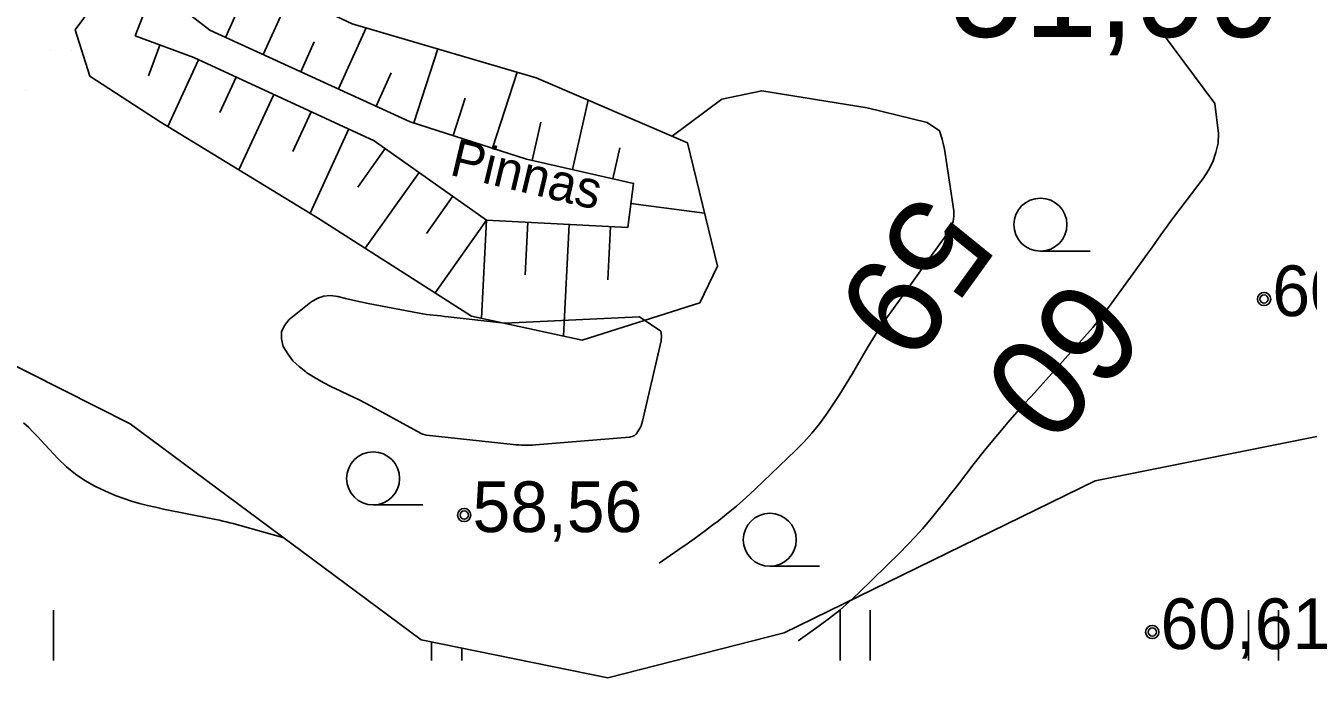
# Model space of a CAD drawing. Extents: x 532503 to 539665, y 6557663 to 6561526.
# Drawn here: x 535438.1 to 535500.1, y 6559470.5 to 6559502.2 of the extents above; entities that cross this region are included whole.
import ezdxf

# ---------------------------------------------------------------- set-up
doc = ezdxf.new("R2010")
doc.units = 0
for name, color, linetype in [('Default', 7, 'Continuous'), ('GEOLPUNKT', 7, 'Continuous'), ('HALJASTUS', 7, 'Continuous'), ('HORISONTAAL-EH2000', 7, 'Continuous'), ('KORGUS-EH2000', 7, 'Continuous'), ('RELJEEF', 7, 'Continuous')]:
    doc.layers.add(name, color=color, linetype=linetype)

# ---------------------------------------------------------------- blocks, each defined once
blk = doc.blocks.new('POINT_DISPLAY')
at = {"layer": 'Default'}
blk.add_line((0, 0), (0, 0), dxfattribs=at)

msp = doc.modelspace()

# ---------------------------------------------------------------- linework, layer by layer
at = {"layer": 'HALJASTUS'}
for p, q in [((535487.165, 6559491.333), (535489.565, 6559491.333)), ((535454.926, 6559479.07), (535457.326, 6559479.07)), ((535474.092, 6559476.103), (535476.492, 6559476.103)), ((535439.479, 6559471.546), (535439.479, 6559473.982)), ((535477.484, 6559471.546), (535477.484, 6559473.982)), ((535478.941, 6559471.546), (535478.941, 6559473.982)), ((535497.215, 6559471.546), (535497.215, 6559473.982)), ((535498.671, 6559471.546), (535498.671, 6559473.982)), ((535457.753, 6559471.546), (535457.753, 6559472.453)), ((535459.21, 6559471.546), (535459.21, 6559472.156))]:
    msp.add_line(p, q, dxfattribs=at)
msp.add_lwpolyline([(535297.765, 6559425.333), (535293.237, 6559472.388), (535292.11, 6559493.515), (535294.197, 6559495.477), (535329.337, 6559492.847), (535343.026, 6559489.84), (535371.406, 6559495.352), (535400.286, 6559496.521), (535423.657, 6559492.847), (535443.189, 6559482.993), (535457.253, 6559472.555), (535466.268, 6559470.718), (535474.782, 6559472.889), (535489.806, 6559480.237), (535512.343, 6559484.747), (535525.539, 6559485.647)], dxfattribs=at)
for centre in [(535487.165, 6559492.613), (535454.926, 6559480.35), (535474.092, 6559477.383)]:
    msp.add_circle(centre, 1.28, dxfattribs=at)
at = {"layer": 'HORISONTAAL-EH2000'}
for points in [[(535495.591, 6559498.47), (535492.597, 6559502.5), (535492.917, 6559507.664)], [(535482.418, 6559496.737), (535482.287, 6559497.155), (535481.687, 6559497.552), (535478.792, 6559498.26), (535473.707, 6559499.083), (535471.782, 6559498.686), (535469.379, 6559496.884)], [(535489.695, 6559487.636), (535490.101, 6559488.15), (535490.577, 6559488.782), (535492.117, 6559490.903), (535492.308, 6559491.168), (535492.498, 6559491.433), (535492.687, 6559491.699), (535492.875, 6559491.966), (535493.063, 6559492.232), (535493.254, 6559492.496), (535493.448, 6559492.759), (535493.644, 6559493.02), (535495.032, 6559494.849), (535495.287, 6559495.244), (535495.5, 6559495.657), (535495.648, 6559496.097), (535495.753, 6559496.555), (535495.767, 6559497.014), (535495.591, 6559498.47)], [(535482.358, 6559491.751), (535482.401, 6559491.809), (535482.498, 6559491.947), (535482.595, 6559492.084), (535482.691, 6559492.223), (535482.731, 6559492.28), (535482.8, 6559492.393), (535482.861, 6559492.51), (535482.909, 6559492.632), (535482.949, 6559492.758), (535482.975, 6559492.888), (535482.989, 6559493.018), (535482.988, 6559493.149), (535482.977, 6559493.28), (535482.562, 6559496.055), (535482.527, 6559496.26), (535482.486, 6559496.464), (535482.438, 6559496.666), (535482.418, 6559496.737)], [(535468.75, 6559476.25), (535469.651, 6559476.875), (535470.099, 6559477.19), (535470.545, 6559477.51), (535470.986, 6559477.835), (535471.424, 6559478.164), (535471.526, 6559478.241), (535472.006, 6559478.62), (535472.477, 6559479.009), (535472.935, 6559479.414), (535473.384, 6559479.83), (535475.329, 6559481.694), (535475.736, 6559482.108), (535476.126, 6559482.538), (535476.489, 6559482.99), (535476.835, 6559483.457), (535477.161, 6559483.939), (535477.479, 6559484.427), (535477.785, 6559484.922), (535478.082, 6559485.423), (535478.389, 6559485.957), (535478.845, 6559486.721), (535479.317, 6559487.475), (535479.812, 6559488.213), (535479.903, 6559488.343), (535482.358, 6559491.751)], [(535461.296, 6559487.845), (535458.554, 6559488.163), (535458.379, 6559488.182), (535458.203, 6559488.201), (535458.028, 6559488.218), (535457.852, 6559488.234), (535457.676, 6559488.252), (535457.501, 6559488.273), (535457.327, 6559488.3), (535457.153, 6559488.331), (535454.689, 6559488.809), (535454.321, 6559488.884), (535453.954, 6559488.964), (535453.59, 6559489.052), (535453.226, 6559489.144), (535452.875, 6559489.184), (535452.537, 6559489.162), (535452.219, 6559489.046), (535451.914, 6559488.867), (535450.878, 6559488.036), (535450.645, 6559487.745), (535450.503, 6559487.435), (535450.499, 6559487.093), (535450.586, 6559486.731), (535450.801, 6559486.37), (535451.049, 6559486.039), (535451.347, 6559485.751), (535451.678, 6559485.494), (535451.731, 6559485.459), (535452.121, 6559485.216), (535452.517, 6559484.986), (535452.924, 6559484.775), (535453.337, 6559484.576), (535453.765, 6559484.377), (535454.182, 6559484.174), (535454.595, 6559483.963), (535455.004, 6559483.746), (535457.254, 6559482.52), (535457.272, 6559482.51), (535457.291, 6559482.502), (535457.31, 6559482.494), (535457.33, 6559482.487), (535457.449, 6559482.449), (535457.5, 6559482.44), (535461.692, 6559481.989), (535461.827, 6559481.977), (535461.961, 6559481.966), (535462.096, 6559481.96), (535462.23, 6559481.955), (535462.365, 6559481.954), (535462.5, 6559481.957), (535462.634, 6559481.963), (535462.769, 6559481.972), (535467.309, 6559482.345), (535467.328, 6559482.347), (535467.348, 6559482.35), (535467.367, 6559482.354), (535467.386, 6559482.359), (535467.462, 6559482.38), (535467.481, 6559482.386), (535467.498, 6559482.394), (535467.515, 6559482.403), (535467.532, 6559482.414), (535467.611, 6559482.473), (535467.629, 6559482.487), (535467.645, 6559482.503), (535467.66, 6559482.521), (535467.673, 6559482.539), (535467.768, 6559482.694), (535467.823, 6559482.793), (535467.871, 6559482.895), (535467.909, 6559483.002), (535467.94, 6559483.111), (535468.841, 6559486.998), (535468.856, 6559487.236), (535468.826, 6559487.46), (535467.795, 6559488.159), (535461.296, 6559487.845)], [(535475.46, 6559472.5), (535476.48, 6559473.223), (535476.981, 6559473.595), (535477.468, 6559473.983), (535477.937, 6559474.393), (535478.394, 6559474.819), (535480.369, 6559476.75), (535480.746, 6559477.131), (535481.115, 6559477.52), (535481.471, 6559477.92), (535481.818, 6559478.328), (535482.157, 6559478.743), (535482.493, 6559479.161), (535482.825, 6559479.582), (535483.154, 6559480.005), (535483.972, 6559481.069), (535484.531, 6559481.778), (535485.101, 6559482.476), (535485.688, 6559483.161), (535486.287, 6559483.836), (535486.436, 6559484), (535486.896, 6559484.506), (535489.695, 6559487.636)], [(535438.041, 6559483.039), (535438.166, 6559482.928), (535438.286, 6559482.812), (535438.322, 6559482.776), (535438.456, 6559482.637), (535438.59, 6559482.498), (535438.723, 6559482.359), (535438.855, 6559482.218), (535439.711, 6559481.303), (535440.114, 6559480.916), (535440.541, 6559480.562), (535441.003, 6559480.255), (535441.49, 6559479.981), (535441.787, 6559479.834), (535442.147, 6559479.667), (535442.512, 6559479.513), (535442.885, 6559479.377), (535443.262, 6559479.253), (535443.644, 6559479.144), (535444.028, 6559479.042), (535444.415, 6559478.952), (535444.804, 6559478.868), (535447.163, 6559478.399), (535447.331, 6559478.364), (535447.499, 6559478.328), (535447.666, 6559478.289), (535447.833, 6559478.249), (535448, 6559478.207), (535448.166, 6559478.164), (535448.331, 6559478.12), (535448.497, 6559478.074), (535450.56, 6559477.5)]]:
    msp.add_lwpolyline(points, dxfattribs=at)
at = {"layer": 'KORGUS-EH2000'}
for centre, radius in [((535497.971, 6559489.018), 0.32), ((535497.971, 6559489.018), 0.2), ((535459.329, 6559478.579), 0.32), ((535459.329, 6559478.579), 0.2), ((535459.329, 6559478.579), 0.2), ((535492.571, 6559472.925), 0.32), ((535492.571, 6559472.925), 0.2), ((535492.571, 6559472.925), 0.2)]:
    msp.add_circle(centre, radius, dxfattribs=at)
at = {"layer": 'RELJEEF'}
for p, q in [((535449.609, 6559500.834), (535450.931, 6559503.731)), ((535447.79, 6559501.664), (535448.455, 6559503.123)), ((535453.248, 6559499.173), (535454.596, 6559502.126)), ((535451.428, 6559500.003), (535452.085, 6559501.442)), ((535444.622, 6559501.295), (535444.071, 6559499.804)), ((535456.894, 6559497.531), (535458.046, 6559501.11)), ((535446.491, 6559500.585), (535445.005, 6559497.36)), ((535448.307, 6559499.748), (535447.515, 6559498.029)), ((535455.067, 6559498.342), (535455.801, 6559499.949)), ((535460.702, 6559496.306), (535461.885, 6559499.98)), ((535450.124, 6559498.911), (535448.442, 6559495.262)), ((535458.798, 6559496.919), (535459.382, 6559498.732)), ((535464.563, 6559495.275), (535465.322, 6559498.627)), ((535451.94, 6559498.074), (535451.051, 6559496.143)), ((535453.757, 6559497.237), (535451.88, 6559493.164)), ((535462.612, 6559495.717), (535463.033, 6559497.574)), ((535455.513, 6559496.296), (535454.187, 6559494.422)), ((535466.513, 6559494.833), (535466.852, 6559496.329)), ((535457.146, 6559495.141), (535454.548, 6559491.47)), ((535458.779, 6559493.986), (535457.507, 6559492.189)), ((535467.384, 6559493.639), (535470.935, 6559493.171)), ((535460.411, 6559492.831), (535457.923, 6559489.314)), ((535460.411, 6559492.831), (535460.166, 6559488.089)), ((535462.409, 6559492.727), (535462.277, 6559490.194)), ((535464.406, 6559492.624), (535464.127, 6559487.232)), ((535466.403, 6559492.52), (535466.27, 6559489.953))]:
    msp.add_line(p, q, dxfattribs=at)
msp.add_lwpolyline([(535441.242, 6559499.796), (535440.531, 6559502.037), (535443.039, 6559505.429), (535445.583, 6559506.246), (535453.922, 6559502.324), (535462.807, 6559499.708), (535470.109, 6559496.57), (535471.559, 6559490.599), (535470.709, 6559488.832), (535465.03, 6559487.036), (535459.674, 6559488.196), (535452.248, 6559492.939), (535444.639, 6559497.583)], close=True, dxfattribs=at)
for points in [[(535441.242, 6559499.796), (535440.531, 6559502.037), (535443.039, 6559505.429), (535445.583, 6559506.246), (535453.922, 6559502.324), (535462.807, 6559499.708), (535470.109, 6559496.57), (535471.559, 6559490.599), (535470.709, 6559488.832), (535465.03, 6559487.036), (535459.674, 6559488.196), (535452.248, 6559492.939), (535444.639, 6559497.583), (535441.242, 6559499.796)], [(535443.438, 6559501.732), (535444.342, 6559504.114), (535447.036, 6559502.008), (535456.722, 6559497.587), (535462.335, 6559495.78), (535467.512, 6559494.607), (535467.231, 6559492.477), (535460.411, 6559492.831)], [(535443.438, 6559501.732), (535444.342, 6559504.114), (535447.036, 6559502.008), (535456.722, 6559497.587), (535462.335, 6559495.78), (535467.512, 6559494.607), (535467.231, 6559492.477), (535460.411, 6559492.831)], [(535443.438, 6559501.732), (535446.269, 6559500.687), (535454.982, 6559496.672), (535460.411, 6559492.831)], [(535443.438, 6559501.732), (535446.269, 6559500.687), (535454.982, 6559496.672), (535460.411, 6559492.831)]]:
    msp.add_lwpolyline(points, dxfattribs=at)

# ---------------------------------------------------------------- block references
for p in [(535439.361, 6559501.033), (535439.361, 6559501.033), (535440.34, 6559501.033), (535440.34, 6559501.033), (535438.144, 6559499.096)]:
    msp.add_blockref('POINT_DISPLAY', p, dxfattribs=at)

# ---------------------------------------------------------------- texts
at = {"layer": 'GEOLPUNKT'}
msp.add_text('51,99', height=4.8, dxfattribs=at).set_placement((535482.791, 6559501.69))
at = {"layer": 'HORISONTAAL-EH2000'}
for s, rotation, p in [('59', 234.22729, (535481.276, 6559494.354)), ('60', 228.18982, (535488.885, 6559490.33))]:
    msp.add_text(s, height=4.8, rotation=rotation, dxfattribs=at).set_placement(p)
at = {"layer": 'KORGUS-EH2000'}
for s, p in [('60,51 ', (535498.371, 6559488.193)), ('58,56 ', (535459.729, 6559477.754)), ('60,61 ', (535492.971, 6559472.1))]:
    msp.add_text(s, height=2.45, dxfattribs=at).set_placement(p)
at = {"layer": 'RELJEEF'}
msp.add_text('Pinnas', height=1.8, rotation=346.59532, dxfattribs=at).set_placement((535458.566, 6559495.034))

doc.saveas('drawing.dxf')
